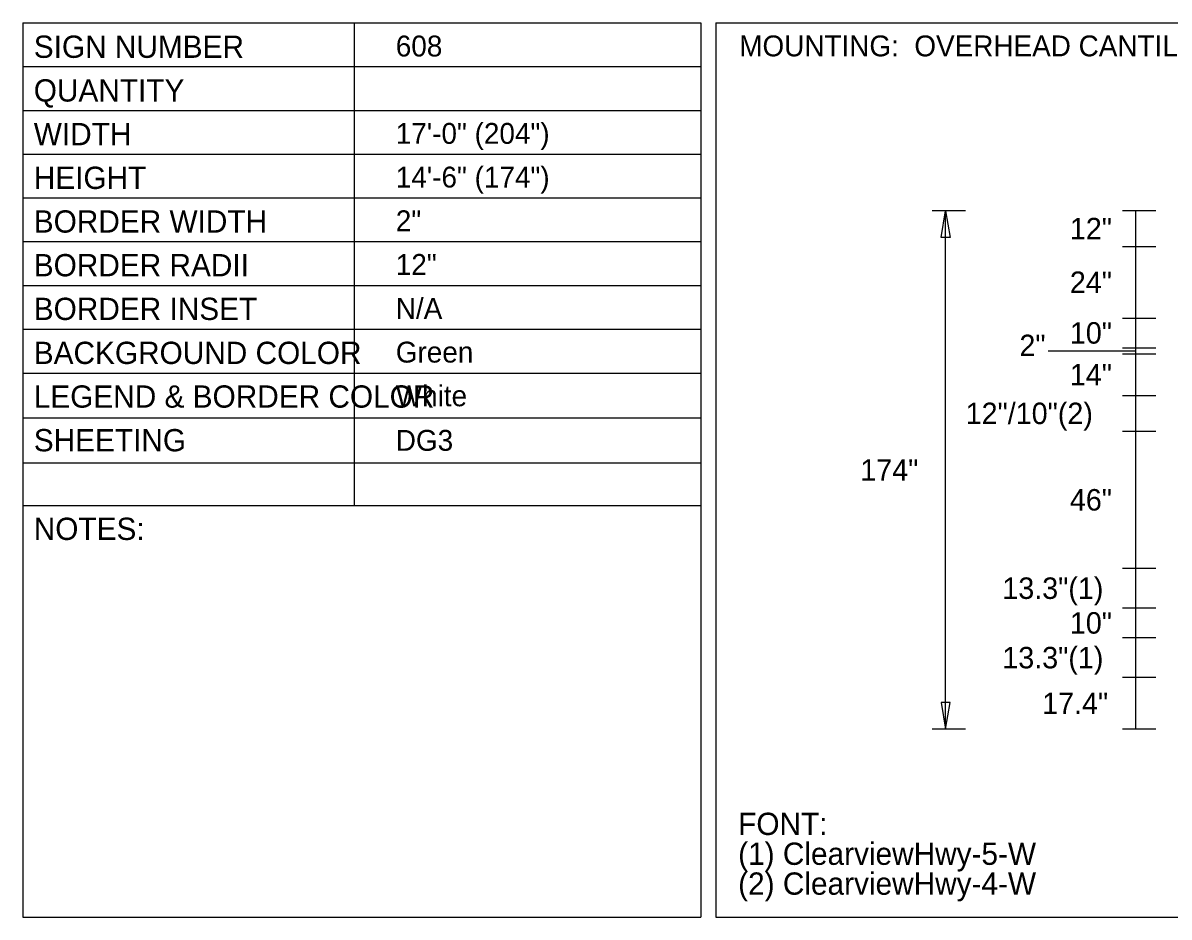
# Model space of a CAD drawing. Extents: x 10268259 to 10268554, y 2141099 to 2141249.
# Drawn here: x 10268395.48 to 10268433.94, y 2141125.53 to 2141155.53 of the extents above; entities that cross this region are included whole.
import ezdxf

# ---------------------------------------------------------------- set-up
doc = ezdxf.new("R2010")
doc.units = 0
for name, color, linetype in [('60', 7, 'Continuous'), ('62', 7, 'Continuous'), ('GSDims', 7, 'Continuous'), ('TextMisc', 7, 'Continuous')]:
    doc.layers.add(name, color=color, linetype=linetype)

msp = doc.modelspace()

# ---------------------------------------------------------------- linework, layer by layer
at = {"layer": '60'}
for p, q in [((10268395.48, 2141155.528), (10268395.48, 2141125.528)), ((10268395.48, 2141155.528), (10268418.23, 2141155.528)), ((10268406.598, 2141155.525), (10268406.598, 2141139.341)), ((10268418.23, 2141155.528), (10268418.23, 2141125.528)), ((10268418.73, 2141155.528), (10268418.73, 2141125.528)), ((10268418.73, 2141155.528), (10268470.98, 2141155.528)), ((10268395.48, 2141154.063), (10268418.23, 2141154.063)), ((10268395.48, 2141152.587), (10268418.23, 2141152.587)), ((10268395.48, 2141151.121), (10268418.23, 2141151.121)), ((10268395.48, 2141149.655), (10268418.23, 2141149.655)), ((10268395.48, 2141148.19), (10268418.23, 2141148.19)), ((10268395.48, 2141146.724), (10268418.23, 2141146.724)), ((10268395.48, 2141145.258), (10268418.23, 2141145.258)), ((10268395.48, 2141143.782), (10268418.23, 2141143.782)), ((10268395.48, 2141142.278), (10268418.23, 2141142.278)), ((10268395.48, 2141140.773), (10268418.23, 2141140.773)), ((10268395.478, 2141139.341), (10268418.229, 2141139.341)), ((10268395.48, 2141125.528), (10268418.23, 2141125.528)), ((10268418.73, 2141125.528), (10268470.98, 2141125.528))]:
    msp.add_line(p, q, dxfattribs=at)
at = {"layer": 'GSDims'}
for p, q in [((10268427.114, 2141149.228), (10268425.989, 2141149.228)), ((10268426.439, 2141131.828), (10268426.439, 2141149.228)), ((10268433.5, 2141149.228), (10268432.375, 2141149.228)), ((10268432.825, 2141131.828), (10268432.825, 2141149.228)), ((10268432.375, 2141148.028), (10268433.5, 2141148.028)), ((10268432.375, 2141145.628), (10268433.5, 2141145.628)), ((10268429.886, 2141144.528), (10268432.825, 2141144.528)), ((10268432.375, 2141144.628), (10268433.5, 2141144.628)), ((10268432.375, 2141144.428), (10268433.5, 2141144.428)), ((10268432.375, 2141143.028), (10268433.5, 2141143.028)), ((10268432.375, 2141141.828), (10268433.5, 2141141.828)), ((10268433.5, 2141137.228), (10268432.375, 2141137.228)), ((10268433.5, 2141135.898), (10268432.375, 2141135.898)), ((10268433.5, 2141134.898), (10268432.375, 2141134.898)), ((10268433.5, 2141133.568), (10268432.375, 2141133.568)), ((10268427.114, 2141131.828), (10268425.989, 2141131.828)), ((10268433.5, 2141131.828), (10268432.375, 2141131.828))]:
    msp.add_line(p, q, dxfattribs=at)
for points in [[(10268426.439, 2141149.228), (10268426.589, 2141148.328), (10268426.289, 2141148.328)], [(10268426.439, 2141131.828), (10268426.589, 2141132.728), (10268426.289, 2141132.728)]]:
    msp.add_lwpolyline(points, close=True, dxfattribs=at)

# ---------------------------------------------------------------- texts
at = {"layer": '62'}
for s, p in [('608', (10268407.991, 2141154.403)), ('MOUNTING:  OVERHEAD CANTILEVER (OC-X)', (10268419.516, 2141154.407)), ('17\'-0" (204")', (10268407.991, 2141151.472)), ('14\'-6" (174")', (10268407.991, 2141150.006)), ('2"', (10268407.991, 2141148.54)), ('12"', (10268407.991, 2141147.074)), ('N/A', (10268407.991, 2141145.599)), ('Green', (10268407.991, 2141144.133)), ('White', (10268407.991, 2141142.667)), ('DG3', (10268407.991, 2141141.173))]:
    msp.add_text(s, height=0.7, dxfattribs=at).set_placement(p)
at = {"layer": 'GSDims'}
for s, p in [('12"', (10268430.611, 2141148.268)), ('24"', (10268430.611, 2141146.468)), ('10"', (10268430.611, 2141144.768)), ('2"', (10268428.918, 2141144.348)), ('14"', (10268430.611, 2141143.368)), ('12"/10"(2)', (10268427.114, 2141142.068)), ('174"', (10268423.578, 2141140.168)), ('46"', (10268430.611, 2141139.168)), ('13.3"(1)', (10268428.344, 2141136.203)), ('10"', (10268430.611, 2141135.038)), ('13.3"(1)', (10268428.344, 2141133.873)), ('17.4"', (10268429.681, 2141132.338))]:
    msp.add_text(s, height=0.72, dxfattribs=at).set_placement(p)
at = {"layer": 'TextMisc'}
for s, height, p in [('SIGN NUMBER', 0.74756, (10268395.842, 2141154.356)), ('QUANTITY', 0.7476, (10268395.842, 2141152.89)), ('WIDTH', 0.7476, (10268395.842, 2141151.424)), ('HEIGHT', 0.7476, (10268395.842, 2141149.958)), ('BORDER WIDTH', 0.74756, (10268395.842, 2141148.493)), ('BORDER RADII', 0.74756, (10268395.842, 2141147.027)), ('BORDER INSET', 0.74756, (10268395.842, 2141145.561)), ('BACKGROUND COLOR', 0.74756, (10268395.842, 2141144.085)), ('LEGEND & BORDER COLOR', 0.74756, (10268395.842, 2141142.62)), ('SHEETING', 0.7476, (10268395.842, 2141141.154)), ('NOTES:', 0.7476, (10268395.841, 2141138.181)), ('FONT:', 0.7476, (10268419.48, 2141128.282)), ('(1) ClearviewHwy-5-W', 0.74756, (10268419.48, 2141127.28)), ('(2) ClearviewHwy-4-W', 0.74756, (10268419.48, 2141126.278))]:
    msp.add_text(s, height=height, dxfattribs=at).set_placement(p)

doc.saveas('drawing.dxf')
